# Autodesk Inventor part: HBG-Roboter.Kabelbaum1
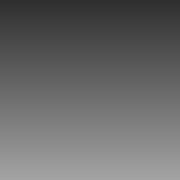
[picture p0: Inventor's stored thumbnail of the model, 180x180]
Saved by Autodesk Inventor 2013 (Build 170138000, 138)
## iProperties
Created: 2012-08
Part Number: HBG-Roboter.Kabelbaum1
Material: Allgemein
Document SubType Name: Modellieren
Designer: rYan
GlobalPropertyList: <PropertyList/>
Author: rYan
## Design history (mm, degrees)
workpoint "Arbeitspunkt6"
workpoint "Arbeitspunkt7"
sketch "Flachbandkabel1"
workpoint "Arbeitspunkt8"
sketch "Skizze11"
  geometry: C1 r 0.05 at (0, 5)
  constraints: 1 centre point
sketch "Skizze12"
  geometry: C1 r 0.05 at (0, -5)
  constraints: 1 centre point
sketch "Skizze13"
  geometry: L1 (0, 6)-(0, -6)
  constraints: 2 end point
feature "Sweeping-Fläche11" dims "d10" = 0
feature "Sweeping-Fläche12" dims "d11" = 0
feature "Sweeping-Fläche13" dims "d12" = 0
workpoint "Arbeitspunkt9"
workpoint "Arbeitspunkt10"
sketch "Flachbandkabel2"
workpoint "Arbeitspunkt13"
workpoint "Arbeitspunkt14"
workpoint "Arbeitspunkt15"
workpoint "Arbeitspunkt16"
node "Volumenkörper"
node "Oberflächenkörper"
node "Fläche11"
node "Fläche12"
node "Fläche13"
